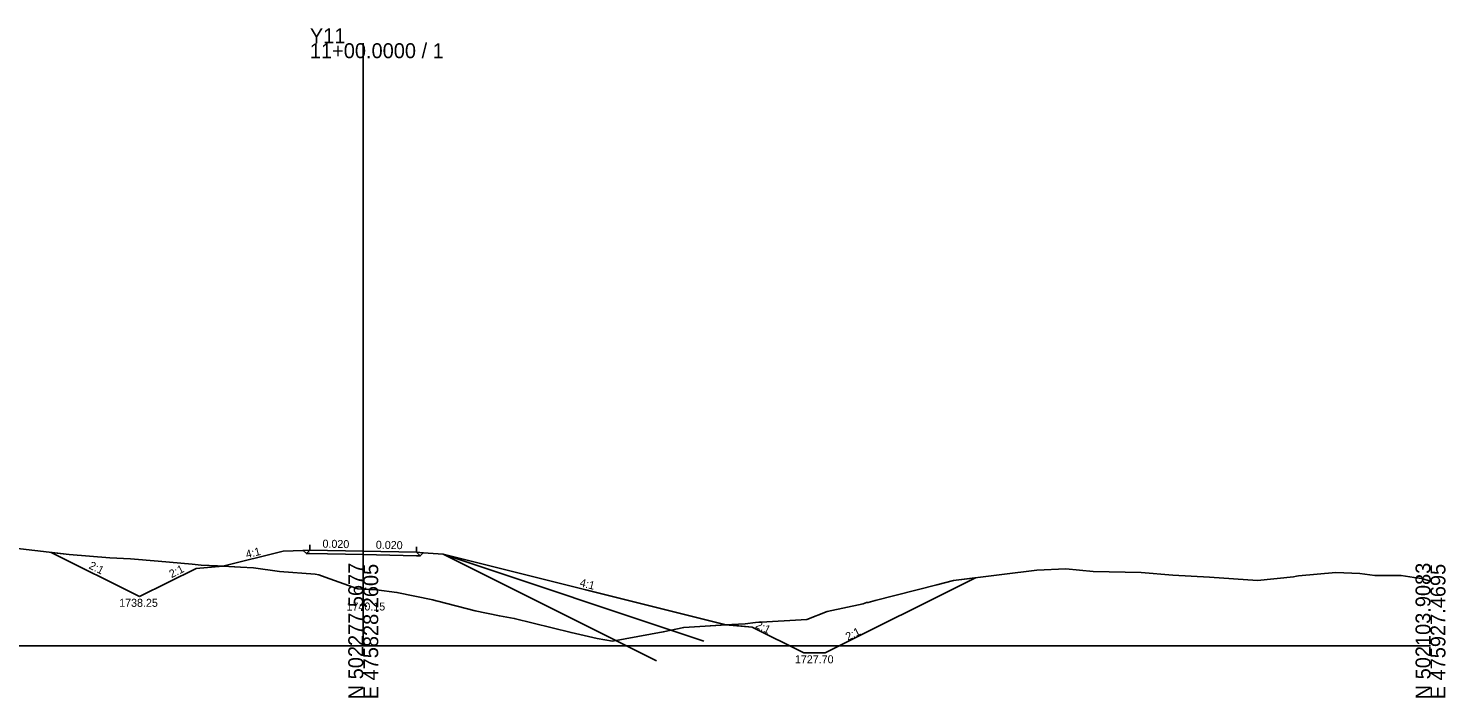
# Model space of a CAD drawing. Extents: x -76 to 353, y -10 to 8186.
# Drawn here: x 87.2 to 352.8, y 1990.3 to 2115.8 of the extents above; entities that cross this region are included whole.
import ezdxf

# ---------------------------------------------------------------- set-up
doc = ezdxf.new("R2010")
doc.units = 0
for name, color, linetype in [('Exist Cross Section Cell', 7, 'Continuous'), ('Exist XS Center Line Elevation Label', 7, 'Continuous'), ('Exist XS Ground Line', 7, 'Continuous'), ('Prop XS DDE', 7, 'Continuous'), ('Prop XS DDE Earthwork Shape', 7, 'Continuous'), ('Prop XS Ditch Standard Text', 7, 'Continuous'), ('Prop XS Dump Level', 7, 'Continuous'), ('Prop XS Earthwork Shape', 7, 'Continuous'), ('Prop XS EOT Tick Mark', 7, 'Continuous'), ('Prop XS Finish Grade', 7, 'Continuous'), ('Prop XS Finish Grade Earthwork', 7, 'Continuous'), ('Prop XS Finish Grade Pavement', 7, 'Continuous'), ('Prop XS Hydro Fill Slope Data', 7, 'Continuous'), ('Prop XS Pvmt Edge Slope', 7, 'Continuous'), ('Prop XS SE Text', 7, 'Continuous'), ('Prop XS Shoulder Borrow Shape', 7, 'Continuous'), ('Prop XS Side Slope Text', 7, 'Continuous'), ('Prop XS Subgrade Earthwork', 7, 'Continuous'), ('Scratch_Level_3', 7, 'Continuous'), ('Scratch_Level_4', 7, 'Continuous')]:
    doc.layers.add(name, color=color, linetype=linetype)

msp = doc.modelspace()

# ---------------------------------------------------------------- linework, layer by layer
at = {"layer": 'Exist Cross Section Cell'}
for p, q in [((150, 2000), (150, 2113.01)), ((-50, 2000), (150, 2000)), ((150, 2000), (350, 2000))]:
    msp.add_line(p, q, dxfattribs=at)
at = {"layer": 'Exist XS Ground Line'}
msp.add_lwpolyline([(84.71, 2018.33), (94.88, 2017.15), (102.52, 2016.53), (106.4, 2016.33), (111.58, 2015.88), (117.92, 2015.33), (119.65, 2015.14), (122.68, 2015), (126.98, 2014.8), (129.44, 2014.63), (134.31, 2013.97), (140.96, 2013.48), (141.65, 2013.32), (142.85, 2012.92), (148.98, 2010.7), (150, 2010.65), (152.48, 2010.54), (156.31, 2010.03), (163.01, 2008.68), (163.64, 2008.49), (164, 2008.43), (170.97, 2006.61), (175.52, 2005.65), (178.3, 2005.17), (188.94, 2002.51), (193.84, 2001.43), (196.73, 2000.92), (206.21, 2002.62), (210.07, 2003.47), (219.05, 2004), (221.59, 2004.16), (223.5, 2004.37), (233.11, 2004.95), (236.95, 2006.48), (243.66, 2007.93), (244.28, 2008.14), (244.63, 2008.13), (245.92, 2008.52), (257.49, 2011.48), (260.62, 2012.25), (269.69, 2013.41), (276.2, 2014.22), (281.69, 2014.46), (286.78, 2013.94), (295.78, 2013.76), (301.7, 2013.28), (308.57, 2012.92), (317.59, 2012.28), (324.32, 2012.96), (324.92, 2013.08), (325.26, 2013.13), (332.25, 2013.78), (336.78, 2013.56), (339.58, 2013.24), (344.48, 2013.23), (346.91, 2012.81), (348.3, 2012.63), (350, 2012.12)], dxfattribs=at)
at = {"layer": 'Prop XS DDE'}
for p, q in [((108.1, 2009.25), (91.53, 2017.54)), ((118.68, 2014.54), (108.1, 2009.25)), ((123.68, 2014.95), (118.68, 2014.54)), ((264.75, 2012.78), (236.59, 1998.7)), ((220.41, 2003.75), (217.91, 2003.96)), ((222.91, 2003.54), (217.91, 2003.96)), ((217.91, 2003.96), (218, 2003.94)), ((232.59, 1998.7), (222.91, 2003.54)), ((232.59, 1998.7), (236.59, 1998.7))]:
    msp.add_line(p, q, dxfattribs=at)
at = {"layer": 'Prop XS DDE Earthwork Shape'}
for p, q in [((91.53, 2017.54), (108.1, 2009.25)), ((108.1, 2009.25), (118.68, 2014.54)), ((118.68, 2014.54), (123.68, 2014.95)), ((123.68, 2014.95), (122.68, 2015))]:
    msp.add_line(p, q, dxfattribs=at)
msp.add_lwpolyline([(122.68, 2015), (119.65, 2015.14), (117.92, 2015.33), (111.58, 2015.88), (106.4, 2016.33), (102.52, 2016.53), (94.88, 2017.15), (91.53, 2017.54)], dxfattribs=at)
for points in [[(220.41, 2003.75), (222.91, 2003.54), (232.59, 1998.7), (236.59, 1998.7), (264.75, 2012.78), (260.62, 2012.25), (257.49, 2011.48), (245.92, 2008.52), (244.63, 2008.13), (244.28, 2008.14), (243.66, 2007.93), (236.95, 2006.48), (233.11, 2004.95), (223.5, 2004.37), (221.59, 2004.16), (219.05, 2004), (218.09, 2003.94)], [(218.09, 2003.94), (219.05, 2004), (221.59, 2004.16), (223.5, 2004.37), (233.11, 2004.95), (236.95, 2006.48), (243.66, 2007.93), (244.28, 2008.14), (244.63, 2008.13), (245.92, 2008.52), (257.49, 2011.48), (260.62, 2012.25), (264.75, 2012.78), (236.59, 1998.7), (232.59, 1998.7), (222.91, 2003.54), (220.41, 2003.75)], [(218.09, 2003.94), (217.91, 2003.96), (218, 2003.94)], [(218, 2003.94), (218.09, 2003.94), (217.91, 2003.96)]]:
    msp.add_lwpolyline(points, close=True, dxfattribs=at)
at = {"layer": 'Prop XS Dump Level'}
for p, q in [((140, 2017.99), (150, 2017.79)), ((150, 2017.79), (160, 2017.59))]:
    msp.add_line(p, q, dxfattribs=at)
at = {"layer": 'Prop XS Earthwork Shape'}
msp.add_lwpolyline([(160, 2016.92), (160.68, 2016.9), (161.26, 2017.48), (165, 2017.19), (218, 2003.94), (210.07, 2003.47), (206.21, 2002.62), (196.73, 2000.92), (193.84, 2001.43), (188.94, 2002.51), (178.3, 2005.17), (175.52, 2005.65), (170.97, 2006.61), (164, 2008.43), (163.64, 2008.49), (163.01, 2008.68), (156.31, 2010.03), (152.48, 2010.54), (150, 2010.65), (148.98, 2010.7), (142.85, 2012.92), (141.65, 2013.32), (140.96, 2013.48), (134.31, 2013.97), (129.44, 2014.63), (126.98, 2014.8), (123.68, 2014.95), (135, 2017.79), (138.74, 2017.93), (139.35, 2017.33), (140, 2017.32), (150, 2017.12)], close=True, dxfattribs=at)
at = {"layer": 'Prop XS EOT Tick Mark'}
for p, q in [((140, 2017.99), (140, 2018.99)), ((160, 2017.59), (160, 2018.59))]:
    msp.add_line(p, q, dxfattribs=at)
at = {"layer": 'Prop XS Finish Grade'}
for p, q in [((140, 2017.99), (138.74, 2017.93)), ((160, 2017.59), (161.26, 2017.48))]:
    msp.add_line(p, q, dxfattribs=at)
at = {"layer": 'Prop XS Finish Grade Earthwork'}
for p, q in [((135, 2017.79), (123.68, 2014.95)), ((138.74, 2017.93), (135, 2017.79)), ((161.26, 2017.48), (165, 2017.19)), ((165, 2017.19), (218, 2003.94))]:
    msp.add_line(p, q, dxfattribs=at)
at = {"layer": 'Prop XS Finish Grade Pavement'}
for p, q in [((140, 2017.99), (150, 2017.79)), ((150, 2017.79), (160, 2017.59))]:
    msp.add_line(p, q, dxfattribs=at)
at = {"layer": 'Prop XS Hydro Fill Slope Data'}
msp.add_line((165, 2017.19), (217.91, 2003.96), dxfattribs=at)
at = {"layer": 'Prop XS Pvmt Edge Slope'}
for p, q in [((140, 2017.99), (139.35, 2017.33)), ((160, 2017.59), (160.68, 2016.9))]:
    msp.add_line(p, q, dxfattribs=at)
at = {"layer": 'Prop XS Shoulder Borrow Shape'}
for points in [[(140, 2017.99), (138.74, 2017.93), (139.35, 2017.33)], [(140, 2017.99), (138.74, 2017.93), (139.35, 2017.33)], [(160, 2017.59), (161.26, 2017.48), (160.68, 2016.9)], [(160, 2017.59), (161.26, 2017.48), (160.68, 2016.9)]]:
    msp.add_lwpolyline(points, close=True, dxfattribs=at)
at = {"layer": 'Prop XS Subgrade Earthwork'}
for p, q in [((139.35, 2017.33), (138.74, 2017.93)), ((140, 2017.32), (139.35, 2017.33)), ((150, 2017.12), (140, 2017.32)), ((160, 2016.92), (150, 2017.12)), ((160, 2016.92), (160.68, 2016.9)), ((160.68, 2016.9), (161.26, 2017.48))]:
    msp.add_line(p, q, dxfattribs=at)
at = {"layer": 'Scratch_Level_3'}
for p, q in [((91.53, 2017.54), (108.1, 2009.25)), ((108.1, 2009.25), (118.68, 2014.54)), ((118.68, 2014.54), (123.68, 2014.95)), ((123.68, 2014.95), (122.68, 2015)), ((236.59, 1998.7), (264.75, 2012.78)), ((264.75, 2012.78), (260.62, 2012.25)), ((222.91, 2003.54), (232.59, 1998.7)), ((232.59, 1998.7), (236.59, 1998.7))]:
    msp.add_line(p, q, dxfattribs=at)
for points in [[(122.68, 2015), (119.65, 2015.14), (117.92, 2015.33), (111.58, 2015.88), (106.4, 2016.33), (102.52, 2016.53), (94.88, 2017.15), (91.53, 2017.54)], [(260.62, 2012.25), (257.49, 2011.48), (245.92, 2008.52), (244.63, 2008.13), (244.28, 2008.14), (243.66, 2007.93), (236.95, 2006.48), (233.11, 2004.95), (223.5, 2004.37), (221.59, 2004.16), (219.05, 2004), (218.09, 2003.94)], [(218.09, 2003.94), (220.41, 2003.75), (222.91, 2003.54)]]:
    msp.add_lwpolyline(points, dxfattribs=at)
at = {"layer": 'Scratch_Level_4'}
for p in [(213.82, 2000.91), (204.94, 1997.22)]:
    msp.add_line(p, (165, 2017.19), dxfattribs=at)

# ---------------------------------------------------------------- texts
at = {"layer": 'Exist Cross Section Cell'}
for s, p in [('Y11', (140, 2113.01)), ('11+00.0000 / 1', (140, 2110.21))]:
    msp.add_text(s, height=2.8, dxfattribs=at).set_placement(p)
for s, p in [('N 502277.5677', (150, 1990)), ('E 475828.2605', (152.8, 1990)), ('N 502103.9083', (350, 1990)), ('E 475927.4695', (352.8, 1990))]:
    msp.add_text(s, height=2.8, rotation=90, dxfattribs=at).set_placement(p)
at = {"layer": 'Exist XS Center Line Elevation Label'}
msp.add_text('1740.15', height=1.5, dxfattribs=at).set_placement((146.86, 2006.65))
at = {"layer": 'Prop XS Ditch Standard Text'}
for s, p in [('1738.25', (104.26, 2007.34)), ('1727.70', (230.89, 1996.75))]:
    msp.add_text(s, height=1.5, dxfattribs=at).set_placement(p)
at = {"layer": 'Prop XS Dump Level'}
for p in [(135, 2017.75), (165, 2017.15)]:
    msp.add_text('Case1', height=0.04, dxfattribs=at).set_placement(p)
at = {"layer": 'Prop XS SE Text'}
for p in [(142.35, 2018.44), (152.35, 2018.24)]:
    msp.add_text('0.020', height=1.5, rotation=358.8542, dxfattribs=at).set_placement(p)
at = {"layer": 'Prop XS Side Slope Text'}
for s, rotation, p in [('4:1', 14.0362, (128.18, 2016.42)), ('2:1', 333.4349, (98.45, 2014.61)), ('2:1', 26.5651, (114.08, 2012.71)), ('4:1', 345.9638, (190.47, 2011.21)), ('2:1', 333.4349, (223.37, 2003.49)), ('2:1', 26.5651, (240.84, 2000.97))]:
    msp.add_text(s, height=1.5, rotation=rotation, dxfattribs=at).set_placement(p)

doc.saveas('drawing.dxf')
